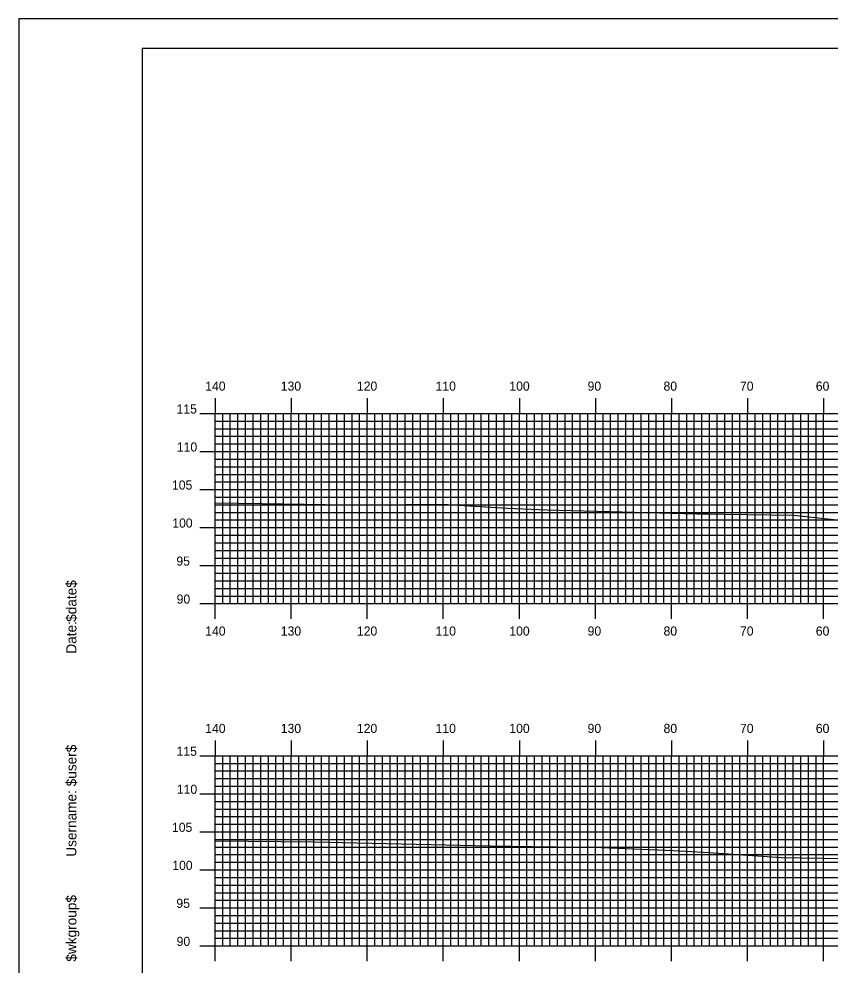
# Model space of a CAD drawing. Extents: x 1773990 to 1774333, y 442591 to 442811.
# Drawn here: x 1773989.9 to 1774096.5, y 442686.2 to 442810.5 of the extents above; entities that cross this region are included whole.
import ezdxf

# ---------------------------------------------------------------- set-up
doc = ezdxf.new("R2010")
doc.units = 0
for name, color, linetype in [('BORDER', 7, 'Continuous'), ('H_V ANNOTATION', 7, 'Continuous'), ('MAJOR', 7, 'Continuous'), ('MINOR', 7, 'Continuous'), ('PLOT BOUNDARY', 7, 'Continuous'), ('S_Roadway_Centerline', 7, 'Continuous')]:
    doc.layers.add(name, color=color, linetype=linetype)

msp = doc.modelspace()

# ---------------------------------------------------------------- linework, layer by layer
at = {"layer": 'BORDER'}
msp.add_lwpolyline([(1774006.06, 442596.67), (1774326.06, 442596.67), (1774326.06, 442806.67), (1774006.06, 442806.67)], close=True, dxfattribs=at)
at = {"layer": 'MAJOR'}
for p, q in [((1774015.66, 442760.67), (1774015.66, 442758.67)), ((1774025.66, 442760.67), (1774025.66, 442758.67)), ((1774035.66, 442760.67), (1774035.66, 442758.67)), ((1774045.66, 442760.67), (1774045.66, 442758.67)), ((1774055.66, 442760.67), (1774055.66, 442758.67)), ((1774065.66, 442760.67), (1774065.66, 442758.67)), ((1774075.66, 442760.67), (1774075.66, 442758.67)), ((1774085.66, 442760.67), (1774085.66, 442758.67)), ((1774095.66, 442760.67), (1774095.66, 442758.67)), ((1774013.65, 442758.67), (1774015.66, 442758.67)), ((1774015.66, 442758.67), (1774295.66, 442758.67)), ((1774015.66, 442733.67), (1774015.66, 442758.67)), ((1774015.66, 442733.67), (1774015.66, 442758.67)), ((1774015.66, 442758.67), (1774295.66, 442758.67)), ((1774025.66, 442733.67), (1774025.66, 442758.67)), ((1774035.66, 442733.67), (1774035.66, 442758.67)), ((1774045.66, 442733.67), (1774045.66, 442758.67)), ((1774055.66, 442733.67), (1774055.66, 442758.67)), ((1774065.66, 442733.67), (1774065.66, 442758.67)), ((1774075.66, 442733.67), (1774075.66, 442758.67)), ((1774085.66, 442733.67), (1774085.66, 442758.67)), ((1774095.66, 442733.67), (1774095.66, 442758.67)), ((1774013.65, 442753.67), (1774015.66, 442753.67)), ((1774015.66, 442753.67), (1774295.66, 442753.67)), ((1774013.65, 442748.67), (1774015.66, 442748.67)), ((1774015.66, 442748.67), (1774295.66, 442748.67)), ((1774013.65, 442743.67), (1774015.66, 442743.67)), ((1774015.66, 442743.67), (1774295.66, 442743.67)), ((1774013.65, 442738.67), (1774015.66, 442738.67)), ((1774015.66, 442738.67), (1774295.66, 442738.67)), ((1774013.65, 442733.67), (1774015.66, 442733.67)), ((1774015.66, 442733.67), (1774295.66, 442733.67)), ((1774015.66, 442733.67), (1774295.66, 442733.67)), ((1774015.66, 442731.66), (1774015.66, 442733.67)), ((1774025.66, 442731.66), (1774025.66, 442733.67)), ((1774035.66, 442731.66), (1774035.66, 442733.67)), ((1774045.66, 442731.66), (1774045.66, 442733.67)), ((1774055.66, 442731.66), (1774055.66, 442733.67)), ((1774065.66, 442731.66), (1774065.66, 442733.67)), ((1774075.66, 442731.66), (1774075.66, 442733.67)), ((1774085.66, 442731.66), (1774085.66, 442733.67)), ((1774095.66, 442731.66), (1774095.66, 442733.67)), ((1774015.66, 442715.67), (1774015.66, 442713.67)), ((1774025.66, 442715.67), (1774025.66, 442713.67)), ((1774035.66, 442715.67), (1774035.66, 442713.67)), ((1774045.66, 442715.67), (1774045.66, 442713.67)), ((1774055.66, 442715.67), (1774055.66, 442713.67)), ((1774065.66, 442715.67), (1774065.66, 442713.67)), ((1774075.66, 442715.67), (1774075.66, 442713.67)), ((1774085.66, 442715.67), (1774085.66, 442713.67)), ((1774095.66, 442715.67), (1774095.66, 442713.67)), ((1774013.65, 442713.67), (1774015.66, 442713.67)), ((1774015.66, 442713.67), (1774295.66, 442713.67)), ((1774015.66, 442688.67), (1774015.66, 442713.67)), ((1774015.66, 442688.67), (1774015.66, 442713.67)), ((1774015.66, 442713.67), (1774295.66, 442713.67)), ((1774025.66, 442688.67), (1774025.66, 442713.67)), ((1774035.66, 442688.67), (1774035.66, 442713.67)), ((1774045.66, 442688.67), (1774045.66, 442713.67)), ((1774055.66, 442688.67), (1774055.66, 442713.67)), ((1774065.66, 442688.67), (1774065.66, 442713.67)), ((1774075.66, 442688.67), (1774075.66, 442713.67)), ((1774085.66, 442688.67), (1774085.66, 442713.67)), ((1774095.66, 442688.67), (1774095.66, 442713.67)), ((1774013.65, 442708.67), (1774015.66, 442708.67)), ((1774015.66, 442708.67), (1774295.66, 442708.67)), ((1774013.65, 442703.67), (1774015.66, 442703.67)), ((1774015.66, 442703.67), (1774295.66, 442703.67)), ((1774013.65, 442698.67), (1774015.66, 442698.67)), ((1774015.66, 442698.67), (1774295.66, 442698.67)), ((1774013.65, 442693.67), (1774015.66, 442693.67)), ((1774015.66, 442693.67), (1774295.66, 442693.67)), ((1774013.65, 442688.67), (1774015.66, 442688.67)), ((1774015.66, 442688.67), (1774295.66, 442688.67)), ((1774015.66, 442688.67), (1774295.66, 442688.67)), ((1774015.66, 442686.66), (1774015.66, 442688.67)), ((1774025.66, 442686.66), (1774025.66, 442688.67)), ((1774035.66, 442686.66), (1774035.66, 442688.67)), ((1774045.66, 442686.66), (1774045.66, 442688.67)), ((1774055.66, 442686.66), (1774055.66, 442688.67)), ((1774065.66, 442686.66), (1774065.66, 442688.67)), ((1774075.66, 442686.66), (1774075.66, 442688.67)), ((1774085.66, 442686.66), (1774085.66, 442688.67)), ((1774095.66, 442686.66), (1774095.66, 442688.67))]:
    msp.add_line(p, q, dxfattribs=at)
at = {"layer": 'MINOR'}
for p, q in [((1774016.66, 442733.67), (1774016.66, 442758.67)), ((1774017.66, 442733.67), (1774017.66, 442758.67)), ((1774018.66, 442733.67), (1774018.66, 442758.67)), ((1774019.66, 442733.67), (1774019.66, 442758.67)), ((1774020.66, 442733.67), (1774020.66, 442758.67)), ((1774021.66, 442733.67), (1774021.66, 442758.67)), ((1774022.66, 442733.67), (1774022.66, 442758.67)), ((1774023.66, 442733.67), (1774023.66, 442758.67)), ((1774024.66, 442733.67), (1774024.66, 442758.67)), ((1774026.66, 442733.67), (1774026.66, 442758.67)), ((1774027.66, 442733.67), (1774027.66, 442758.67)), ((1774028.66, 442733.67), (1774028.66, 442758.67)), ((1774029.66, 442733.67), (1774029.66, 442758.67)), ((1774030.66, 442733.67), (1774030.66, 442758.67)), ((1774031.66, 442733.67), (1774031.66, 442758.67)), ((1774032.66, 442733.67), (1774032.66, 442758.67)), ((1774033.66, 442733.67), (1774033.66, 442758.67)), ((1774034.66, 442733.67), (1774034.66, 442758.67)), ((1774036.66, 442733.67), (1774036.66, 442758.67)), ((1774037.66, 442733.67), (1774037.66, 442758.67)), ((1774038.66, 442733.67), (1774038.66, 442758.67)), ((1774039.66, 442733.67), (1774039.66, 442758.67)), ((1774040.66, 442733.67), (1774040.66, 442758.67)), ((1774041.66, 442733.67), (1774041.66, 442758.67)), ((1774042.66, 442733.67), (1774042.66, 442758.67)), ((1774043.66, 442733.67), (1774043.66, 442758.67)), ((1774044.66, 442733.67), (1774044.66, 442758.67)), ((1774046.66, 442733.67), (1774046.66, 442758.67)), ((1774047.66, 442733.67), (1774047.66, 442758.67)), ((1774048.66, 442733.67), (1774048.66, 442758.67)), ((1774049.66, 442733.67), (1774049.66, 442758.67)), ((1774050.66, 442733.67), (1774050.66, 442758.67)), ((1774051.66, 442733.67), (1774051.66, 442758.67)), ((1774052.66, 442733.67), (1774052.66, 442758.67)), ((1774053.66, 442733.67), (1774053.66, 442758.67)), ((1774054.66, 442733.67), (1774054.66, 442758.67)), ((1774056.66, 442733.67), (1774056.66, 442758.67)), ((1774057.66, 442733.67), (1774057.66, 442758.67)), ((1774058.66, 442733.67), (1774058.66, 442758.67)), ((1774059.66, 442733.67), (1774059.66, 442758.67)), ((1774060.66, 442733.67), (1774060.66, 442758.67)), ((1774061.66, 442733.67), (1774061.66, 442758.67)), ((1774062.66, 442733.67), (1774062.66, 442758.67)), ((1774063.66, 442733.67), (1774063.66, 442758.67)), ((1774064.66, 442733.67), (1774064.66, 442758.67)), ((1774066.66, 442733.67), (1774066.66, 442758.67)), ((1774067.66, 442733.67), (1774067.66, 442758.67)), ((1774068.66, 442733.67), (1774068.66, 442758.67)), ((1774069.66, 442733.67), (1774069.66, 442758.67)), ((1774070.66, 442733.67), (1774070.66, 442758.67)), ((1774071.66, 442733.67), (1774071.66, 442758.67)), ((1774072.66, 442733.67), (1774072.66, 442758.67)), ((1774073.66, 442733.67), (1774073.66, 442758.67)), ((1774074.66, 442733.67), (1774074.66, 442758.67)), ((1774076.66, 442733.67), (1774076.66, 442758.67)), ((1774077.66, 442733.67), (1774077.66, 442758.67)), ((1774078.66, 442733.67), (1774078.66, 442758.67)), ((1774079.66, 442733.67), (1774079.66, 442758.67)), ((1774080.66, 442733.67), (1774080.66, 442758.67)), ((1774081.66, 442733.67), (1774081.66, 442758.67)), ((1774082.66, 442733.67), (1774082.66, 442758.67)), ((1774083.66, 442733.67), (1774083.66, 442758.67)), ((1774084.66, 442733.67), (1774084.66, 442758.67)), ((1774086.66, 442733.67), (1774086.66, 442758.67)), ((1774087.66, 442733.67), (1774087.66, 442758.67)), ((1774088.66, 442733.67), (1774088.66, 442758.67)), ((1774089.66, 442733.67), (1774089.66, 442758.67)), ((1774090.66, 442733.67), (1774090.66, 442758.67)), ((1774091.66, 442733.67), (1774091.66, 442758.67)), ((1774092.66, 442733.67), (1774092.66, 442758.67)), ((1774093.66, 442733.67), (1774093.66, 442758.67)), ((1774094.66, 442733.67), (1774094.66, 442758.67)), ((1774015.66, 442757.67), (1774295.66, 442757.67)), ((1774015.66, 442757.67), (1774017.66, 442757.67)), ((1774015.66, 442756.67), (1774295.66, 442756.67)), ((1774015.66, 442756.67), (1774017.66, 442756.67)), ((1774015.66, 442755.67), (1774295.66, 442755.67)), ((1774015.66, 442755.67), (1774017.66, 442755.67)), ((1774015.66, 442754.67), (1774295.66, 442754.67)), ((1774015.66, 442754.67), (1774017.66, 442754.67)), ((1774015.66, 442752.67), (1774295.66, 442752.67)), ((1774015.66, 442752.67), (1774017.66, 442752.67)), ((1774015.66, 442751.67), (1774295.66, 442751.67)), ((1774015.66, 442751.67), (1774017.66, 442751.67)), ((1774015.66, 442750.67), (1774295.66, 442750.67)), ((1774015.66, 442750.67), (1774017.66, 442750.67)), ((1774015.66, 442749.67), (1774295.66, 442749.67)), ((1774015.66, 442749.67), (1774017.66, 442749.67)), ((1774015.66, 442747.67), (1774295.66, 442747.67)), ((1774015.66, 442747.67), (1774017.66, 442747.67)), ((1774015.66, 442746.67), (1774295.66, 442746.67)), ((1774015.66, 442746.67), (1774017.66, 442746.67)), ((1774015.66, 442745.67), (1774295.66, 442745.67)), ((1774015.66, 442745.67), (1774017.66, 442745.67)), ((1774015.66, 442744.67), (1774295.66, 442744.67)), ((1774015.66, 442744.67), (1774017.66, 442744.67)), ((1774015.66, 442742.67), (1774295.66, 442742.67)), ((1774015.66, 442742.67), (1774017.66, 442742.67)), ((1774015.66, 442741.67), (1774295.66, 442741.67)), ((1774015.66, 442741.67), (1774017.66, 442741.67)), ((1774015.66, 442740.67), (1774295.66, 442740.67)), ((1774015.66, 442740.67), (1774017.66, 442740.67)), ((1774015.66, 442739.67), (1774295.66, 442739.67)), ((1774015.66, 442739.67), (1774017.66, 442739.67)), ((1774015.66, 442737.67), (1774295.66, 442737.67)), ((1774015.66, 442737.67), (1774017.66, 442737.67)), ((1774015.66, 442736.67), (1774295.66, 442736.67)), ((1774015.66, 442736.67), (1774017.66, 442736.67)), ((1774015.66, 442735.67), (1774295.66, 442735.67)), ((1774015.66, 442735.67), (1774017.66, 442735.67)), ((1774015.66, 442734.67), (1774295.66, 442734.67)), ((1774015.66, 442734.67), (1774017.66, 442734.67)), ((1774016.66, 442688.67), (1774016.66, 442713.67)), ((1774017.66, 442688.67), (1774017.66, 442713.67)), ((1774018.66, 442688.67), (1774018.66, 442713.67)), ((1774019.66, 442688.67), (1774019.66, 442713.67)), ((1774020.66, 442688.67), (1774020.66, 442713.67)), ((1774021.66, 442688.67), (1774021.66, 442713.67)), ((1774022.66, 442688.67), (1774022.66, 442713.67)), ((1774023.66, 442688.67), (1774023.66, 442713.67)), ((1774024.66, 442688.67), (1774024.66, 442713.67)), ((1774026.66, 442688.67), (1774026.66, 442713.67)), ((1774027.66, 442688.67), (1774027.66, 442713.67)), ((1774028.66, 442688.67), (1774028.66, 442713.67)), ((1774029.66, 442688.67), (1774029.66, 442713.67)), ((1774030.66, 442688.67), (1774030.66, 442713.67)), ((1774031.66, 442688.67), (1774031.66, 442713.67)), ((1774032.66, 442688.67), (1774032.66, 442713.67)), ((1774033.66, 442688.67), (1774033.66, 442713.67)), ((1774034.66, 442688.67), (1774034.66, 442713.67)), ((1774036.66, 442688.67), (1774036.66, 442713.67)), ((1774037.66, 442688.67), (1774037.66, 442713.67)), ((1774038.66, 442688.67), (1774038.66, 442713.67)), ((1774039.66, 442688.67), (1774039.66, 442713.67)), ((1774040.66, 442688.67), (1774040.66, 442713.67)), ((1774041.66, 442688.67), (1774041.66, 442713.67)), ((1774042.66, 442688.67), (1774042.66, 442713.67)), ((1774043.66, 442688.67), (1774043.66, 442713.67)), ((1774044.66, 442688.67), (1774044.66, 442713.67)), ((1774046.66, 442688.67), (1774046.66, 442713.67)), ((1774047.66, 442688.67), (1774047.66, 442713.67)), ((1774048.66, 442688.67), (1774048.66, 442713.67)), ((1774049.66, 442688.67), (1774049.66, 442713.67)), ((1774050.66, 442688.67), (1774050.66, 442713.67)), ((1774051.66, 442688.67), (1774051.66, 442713.67)), ((1774052.66, 442688.67), (1774052.66, 442713.67)), ((1774053.66, 442688.67), (1774053.66, 442713.67)), ((1774054.66, 442688.67), (1774054.66, 442713.67)), ((1774056.66, 442688.67), (1774056.66, 442713.67)), ((1774057.66, 442688.67), (1774057.66, 442713.67)), ((1774058.66, 442688.67), (1774058.66, 442713.67)), ((1774059.66, 442688.67), (1774059.66, 442713.67)), ((1774060.66, 442688.67), (1774060.66, 442713.67)), ((1774061.66, 442688.67), (1774061.66, 442713.67)), ((1774062.66, 442688.67), (1774062.66, 442713.67)), ((1774063.66, 442688.67), (1774063.66, 442713.67)), ((1774064.66, 442688.67), (1774064.66, 442713.67)), ((1774066.66, 442688.67), (1774066.66, 442713.67)), ((1774067.66, 442688.67), (1774067.66, 442713.67)), ((1774068.66, 442688.67), (1774068.66, 442713.67)), ((1774069.66, 442688.67), (1774069.66, 442713.67)), ((1774070.66, 442688.67), (1774070.66, 442713.67)), ((1774071.66, 442688.67), (1774071.66, 442713.67)), ((1774072.66, 442688.67), (1774072.66, 442713.67)), ((1774073.66, 442688.67), (1774073.66, 442713.67)), ((1774074.66, 442688.67), (1774074.66, 442713.67)), ((1774076.66, 442688.67), (1774076.66, 442713.67)), ((1774077.66, 442688.67), (1774077.66, 442713.67)), ((1774078.66, 442688.67), (1774078.66, 442713.67)), ((1774079.66, 442688.67), (1774079.66, 442713.67)), ((1774080.66, 442688.67), (1774080.66, 442713.67)), ((1774081.66, 442688.67), (1774081.66, 442713.67)), ((1774082.66, 442688.67), (1774082.66, 442713.67)), ((1774083.66, 442688.67), (1774083.66, 442713.67)), ((1774084.66, 442688.67), (1774084.66, 442713.67)), ((1774086.66, 442688.67), (1774086.66, 442713.67)), ((1774087.66, 442688.67), (1774087.66, 442713.67)), ((1774088.66, 442688.67), (1774088.66, 442713.67)), ((1774089.66, 442688.67), (1774089.66, 442713.67)), ((1774090.66, 442688.67), (1774090.66, 442713.67)), ((1774091.66, 442688.67), (1774091.66, 442713.67)), ((1774092.66, 442688.67), (1774092.66, 442713.67)), ((1774093.66, 442688.67), (1774093.66, 442713.67)), ((1774094.66, 442688.67), (1774094.66, 442713.67)), ((1774015.66, 442712.67), (1774295.66, 442712.67)), ((1774015.66, 442712.67), (1774017.66, 442712.67)), ((1774015.66, 442711.67), (1774295.66, 442711.67)), ((1774015.66, 442711.67), (1774017.66, 442711.67)), ((1774015.66, 442710.67), (1774295.66, 442710.67)), ((1774015.66, 442710.67), (1774017.66, 442710.67)), ((1774015.66, 442709.67), (1774295.66, 442709.67)), ((1774015.66, 442709.67), (1774017.66, 442709.67)), ((1774015.66, 442707.67), (1774295.66, 442707.67)), ((1774015.66, 442707.67), (1774017.66, 442707.67)), ((1774015.66, 442706.67), (1774295.66, 442706.67)), ((1774015.66, 442706.67), (1774017.66, 442706.67)), ((1774015.66, 442705.67), (1774295.66, 442705.67)), ((1774015.66, 442705.67), (1774017.66, 442705.67)), ((1774015.66, 442704.67), (1774295.66, 442704.67)), ((1774015.66, 442704.67), (1774017.66, 442704.67)), ((1774015.66, 442702.67), (1774295.66, 442702.67)), ((1774015.66, 442702.67), (1774017.66, 442702.67)), ((1774015.66, 442701.67), (1774295.66, 442701.67)), ((1774015.66, 442701.67), (1774017.66, 442701.67)), ((1774015.66, 442700.67), (1774295.66, 442700.67)), ((1774015.66, 442700.67), (1774017.66, 442700.67)), ((1774015.66, 442699.67), (1774295.66, 442699.67)), ((1774015.66, 442699.67), (1774017.66, 442699.67)), ((1774015.66, 442697.67), (1774295.66, 442697.67)), ((1774015.66, 442697.67), (1774017.66, 442697.67)), ((1774015.66, 442696.67), (1774295.66, 442696.67)), ((1774015.66, 442696.67), (1774017.66, 442696.67)), ((1774015.66, 442695.67), (1774295.66, 442695.67)), ((1774015.66, 442695.67), (1774017.66, 442695.67)), ((1774015.66, 442694.67), (1774295.66, 442694.67)), ((1774015.66, 442694.67), (1774017.66, 442694.67)), ((1774015.66, 442692.67), (1774295.66, 442692.67)), ((1774015.66, 442692.67), (1774017.66, 442692.67)), ((1774015.66, 442691.67), (1774295.66, 442691.67)), ((1774015.66, 442691.67), (1774017.66, 442691.67)), ((1774015.66, 442690.67), (1774295.66, 442690.67)), ((1774015.66, 442690.67), (1774017.66, 442690.67)), ((1774015.66, 442689.67), (1774295.66, 442689.67)), ((1774015.66, 442689.67), (1774017.66, 442689.67))]:
    msp.add_line(p, q, dxfattribs=at)
at = {"layer": 'PLOT BOUNDARY'}
msp.add_lwpolyline([(1773989.87, 442590.55), (1774329.87, 442590.55), (1774329.87, 442810.55), (1773989.87, 442810.55)], close=True, dxfattribs=at)
at = {"layer": 'S_Roadway_Centerline'}
for points in [[(1774015.66, 442746.91), (1774021.87, 442746.85), (1774032.9, 442746.67), (1774034.21, 442746.66), (1774035.51, 442746.66), (1774045.56, 442746.75), (1774054.12, 442746.23), (1774059.29, 442746.02), (1774078.99, 442745.5), (1774080.61, 442745.48), (1774082.55, 442745.43), (1774091.73, 442745.31), (1774101.03, 442744.28), (1774103.52, 442744.03), (1774106.11, 442743.9), (1774122.14, 442743.51), (1774130.47, 442743.47), (1774145.1, 442743.4), (1774153.71, 442743.43), (1774168.45, 442743.62), (1774177.51, 442743.43), (1774190.12, 442743.16), (1774200.85, 442743.13), (1774211.65, 442743.19)], [(1774015.66, 442702.47), (1774028.68, 442702.35), (1774034.29, 442702.23), (1774051.85, 442701.82), (1774057.39, 442701.74), (1774066.42, 442701.59), (1774075.91, 442701.2), (1774080.6, 442700.97), (1774090.14, 442700.31), (1774100.84, 442700.13)]]:
    msp.add_lwpolyline(points, dxfattribs=at)

# ---------------------------------------------------------------- texts
at = {"layer": 'BORDER'}
for s, p in [('$date$', (1773997.43, 442731.28)), ('Date:', (1773997.43, 442727.1)), ('$user$', (1773997.43, 442709.65)), ('Username:', (1773997.43, 442700.4)), ('$wkgroup$', (1773997.43, 442686.6))]:
    msp.add_text(s, height=1.339, rotation=90, dxfattribs=at).set_placement(p)
at = {"layer": 'H_V ANNOTATION'}
for s, p in [('140', (1774014.36, 442761.67)), ('130', (1774024.29, 442761.67)), ('120', (1774034.3, 442761.67)), ('110', (1774044.64, 442761.67)), ('100', (1774054.34, 442761.67)), ('90', (1774064.63, 442761.67)), ('80', (1774074.61, 442761.67)), ('70', (1774084.66, 442761.67)), ('60', (1774094.63, 442761.67)), ('115', (1774010.59, 442758.67)), ('110', (1774010.63, 442753.67)), ('105', (1774009.99, 442748.67)), ('100', (1774010.03, 442743.67)), ('95', (1774010.57, 442738.67)), ('90', (1774010.6, 442733.67)), ('140', (1774014.36, 442729.47)), ('130', (1774024.29, 442729.47)), ('120', (1774034.3, 442729.47)), ('110', (1774044.64, 442729.47)), ('100', (1774054.34, 442729.47)), ('90', (1774064.63, 442729.47)), ('80', (1774074.61, 442729.47)), ('70', (1774084.66, 442729.47)), ('60', (1774094.63, 442729.47)), ('140', (1774014.36, 442716.67)), ('130', (1774024.29, 442716.67)), ('120', (1774034.3, 442716.67)), ('110', (1774044.64, 442716.67)), ('100', (1774054.34, 442716.67)), ('90', (1774064.63, 442716.67)), ('80', (1774074.61, 442716.67)), ('70', (1774084.66, 442716.67)), ('60', (1774094.63, 442716.67)), ('115', (1774010.59, 442713.67)), ('110', (1774010.63, 442708.67)), ('105', (1774009.99, 442703.67)), ('100', (1774010.03, 442698.67)), ('95', (1774010.57, 442693.67)), ('90', (1774010.6, 442688.67))]:
    msp.add_text(s, height=1.2, dxfattribs=at).set_placement(p)
at = {"layer": 'MAJOR'}
for p in [(1774015.65, 442733.67), (1774015.65, 442688.67)]:
    msp.add_text('-', height=0.012, dxfattribs=at).set_placement(p)

doc.saveas('drawing.dxf')
